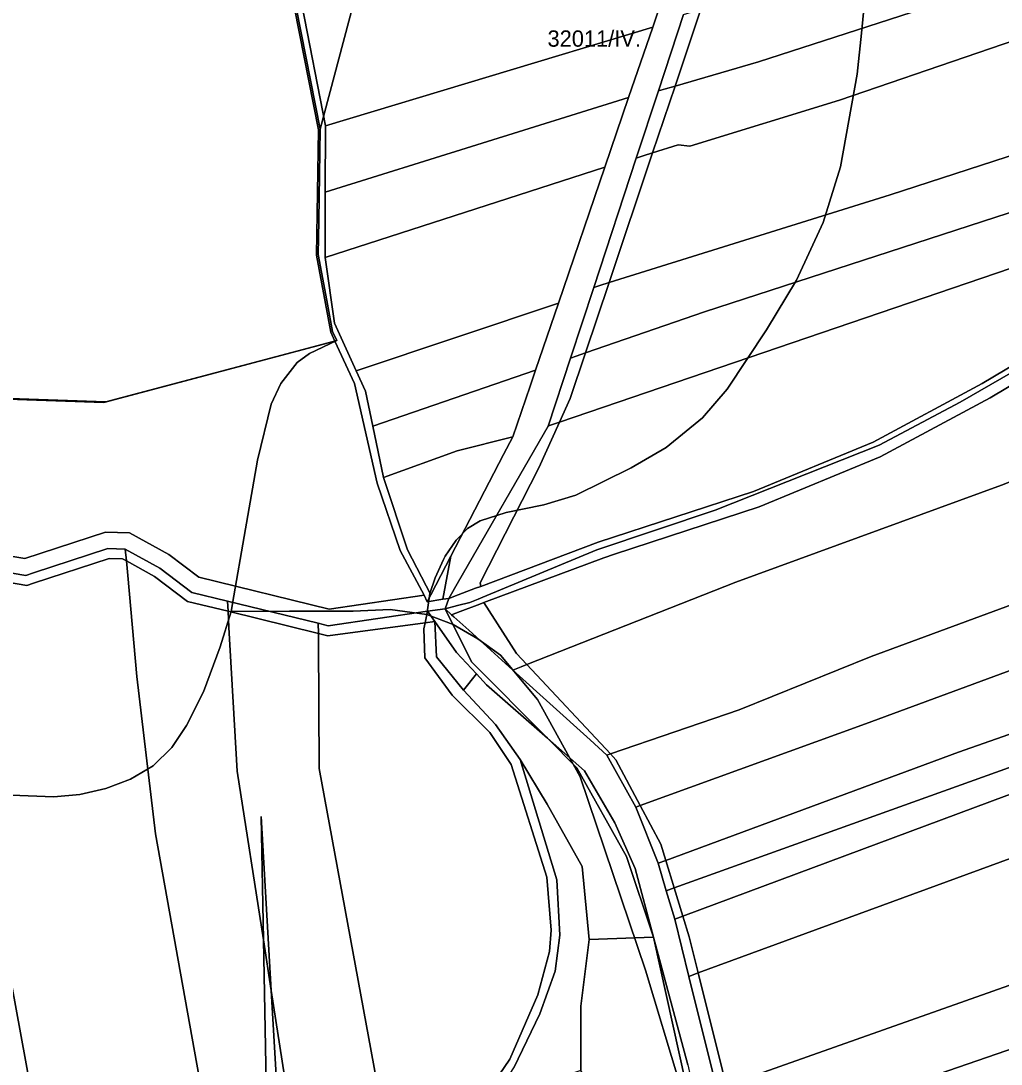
# Model space of a CAD drawing. Extents: x -535894 to -532834, y -1165802 to -1163645.
# Drawn here: x -534170.3 to -533869.9, y -1164507.5 to -1164187.8 of the extents above; entities that cross this region are included whole.
import ezdxf

# ---------------------------------------------------------------- set-up
doc = ezdxf.new("R2010")
doc.units = 0
for name, color, linetype in [('95560013', 7, 'Continuous'), ('95610013', 7, 'Continuous'), ('95620013', 7, 'Continuous'), ('95630013', 7, 'Continuous'), ('95640013', 7, 'Continuous'), ('95660013', 7, 'Continuous')]:
    doc.layers.add(name, color=color, linetype=linetype)

msp = doc.modelspace()

# ---------------------------------------------------------------- linework, layer by layer
at = {"layer": '95560013'}
for points in [[(-533787.38, -1164141.47), (-533783.44, -1164148.24), (-533944.24, -1164200.35), (-533969.8, -1164207.76), (-533961.89, -1164184.21), (-533957.22, -1164182.74), (-533952.85, -1164183.05), (-533791.66, -1164132.02)], [(-534084.16, -1164182.76), (-533962.05, -1164145.52), (-533976.56, -1164189.37), (-533976.67, -1164189.68), (-534076.92, -1164219.96)], [(-533774.86, -1164162.96), (-533792.93, -1164169.52), (-533834.65, -1164183.03), (-533919.48, -1164212.04), (-533965.3, -1164226.17), (-533968.9, -1164225.77), (-533976.69, -1164228.26), (-533969.8, -1164207.76), (-533944.24, -1164200.35), (-533783.44, -1164148.24)], [(-533772.63, -1164166.78), (-533758.05, -1164191.21), (-533828.47, -1164216.61), (-533903.93, -1164241.06), (-533990.05, -1164268), (-533976.69, -1164228.26), (-533968.9, -1164225.77), (-533965.3, -1164226.17), (-533919.48, -1164212.04), (-533834.65, -1164183.03), (-533792.93, -1164169.52), (-533774.86, -1164162.96)], [(-533984.05, -1164211.29), (-534076.98, -1164240.23), (-534076.92, -1164219.96), (-533976.67, -1164189.68)], [(-533758.05, -1164191.21), (-533750.29, -1164204.21), (-533855.48, -1164242.69), (-533960.81, -1164276.96), (-533997.28, -1164289.55), (-533990.05, -1164268), (-533903.93, -1164241.06), (-533828.47, -1164216.61)], [(-533750.29, -1164204.21), (-533749.2, -1164206.03), (-533740.96, -1164217.33), (-533822.24, -1164248.38), (-534005.27, -1164310.75), (-534001.99, -1164303.55), (-533997.28, -1164289.55), (-533960.81, -1164276.96), (-533855.48, -1164242.69)], [(-533991.32, -1164232.59), (-534077.04, -1164260.25), (-534076.98, -1164240.23), (-533984.05, -1164211.29)], [(-533740.96, -1164217.33), (-533728.64, -1164234.23), (-533826.92, -1164269.88), (-533875.75, -1164298.94), (-533909.08, -1164316.88), (-533945.82, -1164332.01), (-533993.34, -1164347.57), (-534029.36, -1164361.07), (-534029.56, -1164360.01), (-534011.6, -1164324.7), (-534005.27, -1164310.75), (-533822.24, -1164248.38)], [(-534077.04, -1164260.25), (-533991.32, -1164232.59), (-534005.58, -1164274.33), (-534067.53, -1164295.01), (-534074.17, -1164280.41)], [(-533725.58, -1164238.43), (-533721.71, -1164243.75), (-533702.69, -1164269.23), (-533789.34, -1164298.55), (-533869.79, -1164330.09), (-533951.16, -1164359.78), (-534015.26, -1164385.02), (-534018.44, -1164381.61), (-534028.41, -1164366.06), (-533991.67, -1164352.29), (-533988.41, -1164351.22), (-533944.08, -1164336.7), (-533906.95, -1164321.42), (-533873.3, -1164303.3), (-533824.77, -1164274.42)], [(-533702.69, -1164269.23), (-533701.48, -1164270.84), (-533677.32, -1164297.76), (-533708.08, -1164308.33), (-533801.45, -1164342.6), (-533909.7, -1164382.52), (-533950.19, -1164398.94), (-533989.65, -1164412.42), (-534015.26, -1164385.02), (-533951.16, -1164359.78), (-533869.79, -1164330.09), (-533789.34, -1164298.55)], [(-534012.59, -1164294.86), (-534062.46, -1164311.93), (-534064.68, -1164301.3), (-534067.53, -1164295.01), (-534005.58, -1164274.33)], [(-534014.24, -1164299.69), (-534019.56, -1164315.28), (-534036.63, -1164319.55), (-534059.17, -1164327.71), (-534062.46, -1164311.93), (-534012.59, -1164294.86)], [(-533677.32, -1164297.76), (-533673.2, -1164302.34), (-533662.64, -1164312.76), (-533781.1, -1164355.1), (-533911.43, -1164403.24), (-533980.48, -1164428.25), (-533987.96, -1164414.23), (-533989.65, -1164412.42), (-533950.19, -1164398.94), (-533909.7, -1164382.52), (-533801.45, -1164342.6), (-533708.08, -1164308.33)], [(-533662.64, -1164312.76), (-533647.79, -1164327.4), (-533741.83, -1164360.18), (-533823.07, -1164390.81), (-533882.99, -1164411.89), (-533972.65, -1164445.05), (-533974.15, -1164440.11), (-533980.48, -1164428.25), (-533911.43, -1164403.24), (-533781.1, -1164355.1)], [(-534036.63, -1164319.55), (-534019.56, -1164315.28), (-534022.34, -1164320.65), (-534038.5, -1164351.85), (-534044.64, -1164363.71), (-534051.85, -1164349.86), (-534059.17, -1164327.71)], [(-533647.79, -1164327.4), (-533639.6, -1164334.73), (-533805.02, -1164394.18), (-533970.07, -1164453.5), (-533972.65, -1164445.05), (-533882.99, -1164411.89), (-533823.07, -1164390.81), (-533741.83, -1164360.18)], [(-534252.63, -1164335.54), (-534225.01, -1164346.8), (-534212.04, -1164352.1), (-534196.56, -1164357.78), (-534194.29, -1164358.08), (-534183.63, -1164425.89), (-534161.35, -1164546.99), (-534154.51, -1164595.51), (-534134.42, -1164692.7), (-534129.11, -1164725.09), (-534140.42, -1164734.83), (-534159.42, -1164746.94), (-534171.37, -1164752.69), (-534189.15, -1164673.8), (-534206.45, -1164583.63), (-534218.39, -1164524.52), (-534233.53, -1164444.63), (-534246.42, -1164381.6)], [(-533639.6, -1164334.73), (-533632.43, -1164341.14), (-533868.12, -1164425.2), (-533967.42, -1164462.17), (-533970.07, -1164453.5), (-533805.02, -1164394.18)], [(-533632.43, -1164341.14), (-533625.55, -1164347.3), (-533616.81, -1164354.28), (-533723.42, -1164393.06), (-533771.52, -1164411.45), (-533810.55, -1164423.74), (-533962.73, -1164479.54), (-533965.5, -1164468.47), (-533967.42, -1164462.17), (-533868.12, -1164425.2)], [(-534143.2, -1164352.52), (-534139.1, -1164352.62), (-534137.95, -1164353.25), (-534137.54, -1164357.79), (-534134.7, -1164388.64), (-534128.98, -1164436.89), (-534104.44, -1164574.12), (-534091.65, -1164672.4), (-534102.21, -1164694.14), (-534107.73, -1164701.96), (-534116.22, -1164713.99), (-534129.11, -1164725.09), (-534134.42, -1164692.7), (-534154.51, -1164595.51), (-534161.35, -1164546.99), (-534183.63, -1164425.89), (-534194.29, -1164358.08), (-534194.56, -1164356.33), (-534168.47, -1164360.79), (-534166.4, -1164360.11)], [(-534137.95, -1164353.25), (-534129.34, -1164358.01), (-534119.2, -1164365.67), (-534106.79, -1164368.71), (-534106.51, -1164373.68), (-534103.98, -1164417.66), (-534095.97, -1164469.37), (-534094.19, -1164562.4), (-534073.88, -1164626.77), (-534073.21, -1164632.31), (-534077.99, -1164644.3), (-534091.65, -1164672.4), (-534104.44, -1164574.12), (-534128.98, -1164436.89), (-534134.7, -1164388.64), (-534137.54, -1164357.79)], [(-533616.81, -1164354.28), (-533585.87, -1164379.01), (-533582.28, -1164381.75), (-533655.23, -1164406.66), (-533798.86, -1164459.07), (-533954.44, -1164514.16), (-533955.24, -1164509.41), (-533962.73, -1164479.54), (-533810.55, -1164423.74), (-533771.52, -1164411.45), (-533723.42, -1164393.06)], [(-534106.79, -1164368.71), (-534079.11, -1164375.48), (-534079.08, -1164377.79), (-534078.82, -1164416.91), (-534053.31, -1164555.72), (-534059.57, -1164593.91), (-534068.68, -1164620.97), (-534070.19, -1164624.73), (-534076.71, -1164603.32), (-534082.07, -1164559.02), (-534093.57, -1164484.87), (-534096.68, -1164431.59), (-534095.97, -1164469.37), (-534103.98, -1164417.66), (-534106.51, -1164373.68)], [(-534046.81, -1164374.1), (-534046.48, -1164382.99), (-534038.12, -1164394.46), (-534026.55, -1164405.86), (-534020.05, -1164415.62), (-534009.16, -1164450.14), (-534007.77, -1164466.45), (-534008.34, -1164472.95), (-534011.87, -1164486.24), (-534020.48, -1164505.94), (-534030.05, -1164520.02), (-534042.53, -1164532.59), (-534051.39, -1164544.05), (-534053.31, -1164555.72), (-534078.82, -1164416.91), (-534079.08, -1164377.79), (-534079.11, -1164375.48), (-534076.23, -1164376.18), (-534046.42, -1164372.25)], [(-533582.28, -1164381.75), (-533564.8, -1164395.06), (-533671.49, -1164431.9), (-533847.42, -1164496.13), (-533951.43, -1164531.95), (-533954.44, -1164514.16), (-533798.86, -1164459.07), (-533655.23, -1164406.66)], [(-533564.8, -1164395.06), (-533548.26, -1164407.66), (-533732.91, -1164473.02), (-533829.26, -1164508.78), (-533948.58, -1164548.78), (-533951.43, -1164531.95), (-533847.42, -1164496.13), (-533671.49, -1164431.9)], [(-534017.28, -1164414.13), (-534009.02, -1164427.79), (-533998.31, -1164446.91), (-533996.14, -1164469.25), (-533998.67, -1164489.69), (-533998.71, -1164509.47), (-534016.41, -1164515.43), (-534025.67, -1164518.54), (-534019.18, -1164508.64), (-534011.21, -1164492.06), (-534006.55, -1164479.03), (-534005.18, -1164467.96), (-534006.06, -1164451.03)], [(-533996.14, -1164469.25), (-533976.42, -1164468.54), (-533966.49, -1164513.4), (-533957.65, -1164563.22), (-533992.16, -1164564.37), (-533995.59, -1164548.2), (-533996.11, -1164524.23), (-533996.35, -1164513.15), (-533998.71, -1164509.47), (-533998.67, -1164489.69)], [(-534093.57, -1164484.87), (-534082.07, -1164559.02), (-534076.71, -1164603.32), (-534088.99, -1164563.04)]]:
    msp.add_lwpolyline(points, close=True, dxfattribs=at)
for points in [[(-534177.29, -1164303.6), (-534144.82, -1164304.74), (-534074.04, -1164285.93), (-534068.03, -1164298.87), (-534061.1, -1164329.42), (-534054.06, -1164350.04), (-534046.67, -1164363.75), (-534075.84, -1164368.05), (-534115.69, -1164358.28), (-534124.97, -1164351.29), (-534136.93, -1164344.68), (-534144.37, -1164344.48), (-534169.08, -1164352.57), (-534194.02, -1164348.32)], [(-534030.05, -1164520.02), (-534020.48, -1164505.94), (-534011.87, -1164486.24), (-534008.34, -1164472.95), (-534007.77, -1164466.45), (-534009.16, -1164450.14), (-534020.05, -1164415.62), (-534026.55, -1164405.86), (-534038.12, -1164394.46), (-534046.48, -1164382.99), (-534046.81, -1164374.1), (-534046.42, -1164372.25), (-534043.41, -1164371.85), (-534042.96, -1164382.7), (-534034.61, -1164392.91), (-534024.85, -1164403.44), (-534017.28, -1164414.13), (-534006.06, -1164451.03), (-534005.18, -1164467.96), (-534006.55, -1164479.03), (-534011.21, -1164492.06), (-534019.18, -1164508.64)]]:
    msp.add_lwpolyline(points, dxfattribs=at)
at = {"layer": '95610013'}
for points in [[(-534036.75, -1164381.38), (-534030.7, -1164387.91), (-534034.61, -1164392.91), (-534042.96, -1164382.7), (-534043.41, -1164371.85)], [(-534027.62, -1164391.24), (-534008.94, -1164407.6), (-533999.91, -1164416.7), (-533984.74, -1164443.86), (-533976.42, -1164468.54), (-533996.14, -1164469.25), (-533998.31, -1164446.91), (-534009.02, -1164427.79), (-534017.28, -1164414.13), (-534024.85, -1164403.44), (-534034.61, -1164392.91), (-534030.7, -1164387.91)], [(-534095.97, -1164469.37), (-534096.68, -1164431.59), (-534093.57, -1164484.87)], [(-534095.97, -1164469.37), (-534093.57, -1164484.87), (-534088.99, -1164563.04), (-534076.71, -1164603.32), (-534073.88, -1164626.77), (-534094.19, -1164562.4)]]:
    msp.add_lwpolyline(points, close=True, dxfattribs=at)
at = {"layer": '95620013'}
msp.add_lwpolyline([(-534426.2, -1164030.27), (-534134.69, -1164091.75), (-534131.77, -1164097.12), (-534123.86, -1164105.89), (-534115.56, -1164113.93), (-534097.11, -1164148.68), (-534086.47, -1164183.86), (-534079.09, -1164221.21), (-534079.7, -1164259.55), (-534075.33, -1164283.15), (-534074.04, -1164285.93), (-534144.82, -1164304.74), (-534177.29, -1164303.6), (-534197.87, -1164299.21), (-534274.99, -1164277.69), (-534335.13, -1164267.45), (-534369.81, -1164273.2), (-534388.51, -1164274.7), (-534418.8, -1164271.7), (-534422.39, -1164273.15)], close=True, dxfattribs=at)
at = {"layer": '95630013'}
for points in [[(-533728.64, -1164234.23), (-533727.58, -1164235.7), (-533822.68, -1164270.18), (-533882.51, -1164304.67), (-533907.25, -1164317.81), (-533957.54, -1164337.73), (-533993.76, -1164349.87), (-534028.73, -1164364.37), (-534030.17, -1164364.97), (-534032.72, -1164366.02), (-534036.44, -1164366.97), (-534040.3, -1164367.94), (-534039.15, -1164364.74), (-534036.32, -1164363.68), (-534030.92, -1164361.66), (-534029.36, -1164361.07), (-533993.34, -1164347.57), (-533945.82, -1164332.01), (-533909.08, -1164316.88), (-533875.75, -1164298.94), (-533826.92, -1164269.88)], [(-533727.58, -1164235.7), (-533726.88, -1164236.66), (-533725.58, -1164238.43), (-533824.77, -1164274.42), (-533873.3, -1164303.3), (-533906.95, -1164321.42), (-533944.08, -1164336.7), (-533988.41, -1164351.22), (-533991.67, -1164352.29), (-534028.41, -1164366.06), (-534029.63, -1164366.52), (-534035.63, -1164368.77), (-534038.28, -1164369.76), (-534040.3, -1164367.94), (-534036.44, -1164366.97), (-534032.72, -1164366.02), (-534030.17, -1164364.97), (-534028.73, -1164364.37), (-533993.76, -1164349.87), (-533957.54, -1164337.73), (-533907.25, -1164317.81), (-533882.51, -1164304.67), (-533822.68, -1164270.18)]]:
    msp.add_lwpolyline(points, close=True, dxfattribs=at)
msp.add_lwpolyline([(-534194.02, -1164348.32), (-534169.08, -1164352.57), (-534144.37, -1164344.48), (-534136.93, -1164344.68), (-534124.97, -1164351.29), (-534115.69, -1164358.28), (-534075.84, -1164368.05), (-534046.67, -1164363.75), (-534045.73, -1164365.82), (-534040.96, -1164365.04), (-534039.15, -1164364.74), (-534040.3, -1164367.94), (-534045.64, -1164368.65), (-534076.08, -1164373.13), (-534079.15, -1164372.38), (-534106.97, -1164365.57), (-534117.88, -1164362.9), (-534127.7, -1164355.49), (-534138.28, -1164349.65), (-534143.64, -1164349.5), (-534166.42, -1164356.96), (-534168.7, -1164357.7), (-534195.05, -1164353.21)], dxfattribs=at)
at = {"layer": '95640013'}
for points in [[(-533967.21, -1164185.88), (-533974.91, -1164209.24), (-533981.7, -1164229.85), (-533994.76, -1164269.48), (-534001.9, -1164291.14), (-534008.75, -1164311.95), (-534036.17, -1164359.56), (-534039.15, -1164364.74), (-534040.96, -1164365.04), (-534038.5, -1164351.85), (-534022.34, -1164320.65), (-534019.56, -1164315.28), (-534014.24, -1164299.69), (-534012.59, -1164294.86), (-534005.58, -1164274.33), (-533991.32, -1164232.59), (-533984.05, -1164211.29), (-533976.67, -1164189.68), (-533976.56, -1164189.37), (-533962.05, -1164145.52)], [(-534084.16, -1164182.76), (-534076.92, -1164219.96), (-534076.98, -1164240.23), (-534077.04, -1164260.25), (-534074.17, -1164280.41), (-534067.53, -1164295.01), (-534064.68, -1164301.3), (-534062.46, -1164311.93), (-534059.17, -1164327.71), (-534051.85, -1164349.86), (-534044.64, -1164363.71), (-534045.73, -1164365.82), (-534046.67, -1164363.75), (-534054.06, -1164350.04), (-534061.1, -1164329.42), (-534068.03, -1164298.87), (-534074.04, -1164285.93), (-534075.33, -1164283.15), (-534079.7, -1164259.55), (-534079.09, -1164221.21), (-534086.47, -1164183.86)], [(-533965.95, -1164507.66), (-533976.42, -1164468.54), (-533982.04, -1164447.55), (-533988.32, -1164433.5), (-533997.55, -1164417.58), (-534008.94, -1164407.6), (-534032.22, -1164384.15), (-534040.3, -1164367.94), (-534038.28, -1164369.76), (-534037.62, -1164370.37), (-534032.99, -1164374.54), (-534019.55, -1164386.7), (-533995.84, -1164408.14), (-533990.7, -1164412.79), (-533981.89, -1164428.76), (-533975.04, -1164445.93), (-533972.51, -1164454.38), (-533969.91, -1164463.09), (-533965.56, -1164480.59), (-533956.98, -1164515.05)]]:
    msp.add_lwpolyline(points, dxfattribs=at)
for points in [[(-533964.91, -1164185.16), (-533961.89, -1164184.21), (-533969.8, -1164207.76), (-533972.74, -1164208.61), (-533974.91, -1164209.24), (-533967.21, -1164185.88)], [(-533972.74, -1164208.61), (-533969.8, -1164207.76), (-533976.69, -1164228.26), (-533979.6, -1164229.18), (-533981.7, -1164229.85), (-533974.91, -1164209.24)], [(-533976.69, -1164228.26), (-533990.05, -1164268), (-533992.85, -1164268.88), (-533994.76, -1164269.48), (-533981.7, -1164229.85), (-533979.6, -1164229.18)], [(-533992.85, -1164268.88), (-533990.05, -1164268), (-533997.28, -1164289.55), (-534000.08, -1164290.52), (-534001.9, -1164291.14), (-533994.76, -1164269.48)], [(-533997.28, -1164289.55), (-534001.99, -1164303.55), (-534005.27, -1164310.75), (-534008.32, -1164311.79), (-534008.75, -1164311.95), (-534001.9, -1164291.14), (-534000.08, -1164290.52)], [(-534008.32, -1164311.79), (-534005.27, -1164310.75), (-534011.6, -1164324.7), (-534029.56, -1164360.01), (-534029.36, -1164361.07), (-534030.92, -1164361.66), (-534036.32, -1164363.68), (-534039.15, -1164364.74), (-534036.17, -1164359.56), (-534008.75, -1164311.95)], [(-534143.64, -1164349.5), (-534138.28, -1164349.65), (-534137.95, -1164353.25), (-534139.1, -1164352.62), (-534143.2, -1164352.52), (-534166.4, -1164360.11), (-534168.47, -1164360.79), (-534194.56, -1164356.33), (-534195.05, -1164353.21), (-534168.7, -1164357.7), (-534166.42, -1164356.96)], [(-534138.28, -1164349.65), (-534127.7, -1164355.49), (-534117.88, -1164362.9), (-534106.97, -1164365.57), (-534106.79, -1164368.71), (-534119.2, -1164365.67), (-534129.34, -1164358.01), (-534137.95, -1164353.25)], [(-534044.64, -1164363.71), (-534038.5, -1164351.85), (-534040.96, -1164365.04), (-534045.73, -1164365.82)], [(-534106.97, -1164365.57), (-534079.15, -1164372.38), (-534079.11, -1164375.48), (-534106.79, -1164368.71)], [(-534029.63, -1164366.52), (-534028.41, -1164366.06), (-534018.44, -1164381.61), (-534015.26, -1164385.02), (-534017, -1164385.7), (-534019.55, -1164386.7), (-534032.99, -1164374.54), (-534037.62, -1164370.37), (-534038.28, -1164369.76), (-534035.63, -1164368.77)], [(-534046.42, -1164372.25), (-534076.23, -1164376.18), (-534079.11, -1164375.48), (-534079.15, -1164372.38), (-534076.08, -1164373.13), (-534045.64, -1164368.65)], [(-534043.41, -1164371.85), (-534046.42, -1164372.25), (-534045.64, -1164368.65)], [(-534045.64, -1164368.65), (-534040.3, -1164367.94), (-534032.22, -1164384.15), (-534008.94, -1164407.6), (-534027.62, -1164391.24), (-534030.7, -1164387.91), (-534036.75, -1164381.38), (-534043.41, -1164371.85)], [(-534015.26, -1164385.02), (-533989.65, -1164412.42), (-533990.7, -1164412.79), (-533995.84, -1164408.14), (-534019.55, -1164386.7), (-534017, -1164385.7)], [(-534008.94, -1164407.6), (-533997.55, -1164417.58), (-533988.32, -1164433.5), (-533982.04, -1164447.55), (-533976.42, -1164468.54), (-533984.74, -1164443.86), (-533999.91, -1164416.7)], [(-533990.7, -1164412.79), (-533989.65, -1164412.42), (-533987.96, -1164414.23), (-533980.48, -1164428.25), (-533981.89, -1164428.76)], [(-533981.89, -1164428.76), (-533980.48, -1164428.25), (-533974.15, -1164440.11), (-533972.65, -1164445.05), (-533975.04, -1164445.93)], [(-533972.65, -1164445.05), (-533970.07, -1164453.5), (-533972.51, -1164454.38), (-533975.04, -1164445.93)], [(-533972.51, -1164454.38), (-533970.07, -1164453.5), (-533967.42, -1164462.17), (-533969.91, -1164463.09)], [(-533967.42, -1164462.17), (-533965.5, -1164468.47), (-533962.73, -1164479.54), (-533965.56, -1164480.59), (-533969.91, -1164463.09)], [(-533965.95, -1164507.66), (-533960.86, -1164530.62), (-533953.65, -1164563.09), (-533955.52, -1164563.15), (-533957.65, -1164563.22), (-533966.49, -1164513.4), (-533976.42, -1164468.54)], [(-533965.56, -1164480.59), (-533962.73, -1164479.54), (-533955.24, -1164509.41), (-533954.44, -1164514.16), (-533956.98, -1164515.05)]]:
    msp.add_lwpolyline(points, close=True, dxfattribs=at)
at = {"layer": '95660013'}
for points in [[(-534085.899, -1164183.652), (-534078.523, -1164221.003), (-534078.967, -1164248.905), (-534079.133, -1164259.336), (-534077.109, -1164270.25), (-534076.31, -1164274.561), (-534074.756, -1164282.942), (-534073.466, -1164285.721), (-534087.197, -1164289.369), (-534144.242, -1164304.527), (-534176.712, -1164303.379)], [(-533911.92, -1164183.18), (-533912.751, -1164191.59), (-533913.99, -1164204.13), (-533919.09, -1164232.56), (-533924.42, -1164249.6), (-533932.62, -1164267.2), (-533941.78, -1164282.49), (-533953.81, -1164300.65), (-533961.37, -1164309.41), (-533972.52, -1164318.49), (-533983.28, -1164324.779), (-534000.24, -1164333.14), (-534010.079, -1164336.043), (-534010.51, -1164336.17), (-534021.54, -1164338.44), (-534029.55, -1164340.99), (-534033.41, -1164343.38), (-534036.91, -1164346.88), (-534040.26, -1164351.82), (-534040.755, -1164352.882), (-534043.36, -1164358.47), (-534044.92, -1164363.21), (-534045.93, -1164369.732), (-534057.139, -1164368.18), (-534068.447, -1164368.656), (-534087.908, -1164368.7), (-534105.88, -1164368.74), (-534105.047, -1164363.987), (-534101.863, -1164345.809), (-534097.76, -1164322.39), (-534093.54, -1164305.27), (-534090.59, -1164298.9), (-534085.57, -1164292.45), (-534081.87, -1164289.7), (-534073.466, -1164285.721), (-534074.756, -1164282.942), (-534076.31, -1164274.561), (-534077.109, -1164270.25), (-534079.133, -1164259.336), (-534078.967, -1164248.905), (-534078.523, -1164221.003), (-534068.49, -1164182.86)], [(-534068.49, -1164182.86), (-534078.523, -1164221.003), (-534085.899, -1164183.652)], [(-533968.34, -1164513.6), (-533978.86, -1164478.72), (-533998.92, -1164419.47), (-534011.99, -1164395.74), (-534023.29, -1164382.2), (-534030.3, -1164377.1), (-534037.813, -1164372.775), (-534045.93, -1164369.732), (-534044.92, -1164363.21), (-534043.36, -1164358.47), (-534040.755, -1164352.882), (-534040.26, -1164351.82), (-534036.91, -1164346.88), (-534033.41, -1164343.38), (-534029.55, -1164340.99), (-534021.54, -1164338.44), (-534010.51, -1164336.17), (-534010.079, -1164336.043), (-534000.24, -1164333.14), (-533983.28, -1164324.779), (-533972.52, -1164318.49), (-533961.37, -1164309.41), (-533953.81, -1164300.65), (-533941.78, -1164282.49), (-533932.62, -1164267.2), (-533924.42, -1164249.6), (-533919.09, -1164232.56), (-533913.99, -1164204.13), (-533912.751, -1164191.59), (-533911.92, -1164183.18)], [(-534176.712, -1164303.379), (-534144.242, -1164304.527), (-534087.197, -1164289.369), (-534073.466, -1164285.721), (-534081.87, -1164289.7), (-534085.57, -1164292.45), (-534090.59, -1164298.9), (-534093.54, -1164305.27), (-534097.76, -1164322.39), (-534101.863, -1164345.809), (-534105.047, -1164363.987), (-534105.88, -1164368.74), (-534109.15, -1164379.57), (-534114.321, -1164393.43), (-534119.556, -1164403.709), (-534124.012, -1164410.439), (-534129.76, -1164416.106), (-534136.722, -1164420.188), (-534144.278, -1164423.025), (-534152.15, -1164424.81), (-534160.19, -1164425.52), (-534173.231, -1164425.044)], [(-534173.231, -1164425.044), (-534160.19, -1164425.52), (-534152.15, -1164424.81), (-534144.278, -1164423.025), (-534136.722, -1164420.188), (-534129.76, -1164416.106), (-534124.012, -1164410.439), (-534119.556, -1164403.709), (-534114.321, -1164393.43), (-534109.15, -1164379.57), (-534105.88, -1164368.74), (-534087.908, -1164368.7), (-534068.447, -1164368.656), (-534057.139, -1164368.18), (-534045.93, -1164369.732), (-534037.813, -1164372.775), (-534030.3, -1164377.1), (-534023.29, -1164382.2), (-534011.99, -1164395.74), (-533998.92, -1164419.47), (-533978.86, -1164478.72), (-533968.34, -1164513.6)]]:
    msp.add_lwpolyline(points, dxfattribs=at)

# ---------------------------------------------------------------- texts
msp.add_text('32011/IV.', height=5, rotation=0, dxfattribs=at).set_placement((-534008.9, -1164195.699))

doc.saveas('drawing.dxf')
